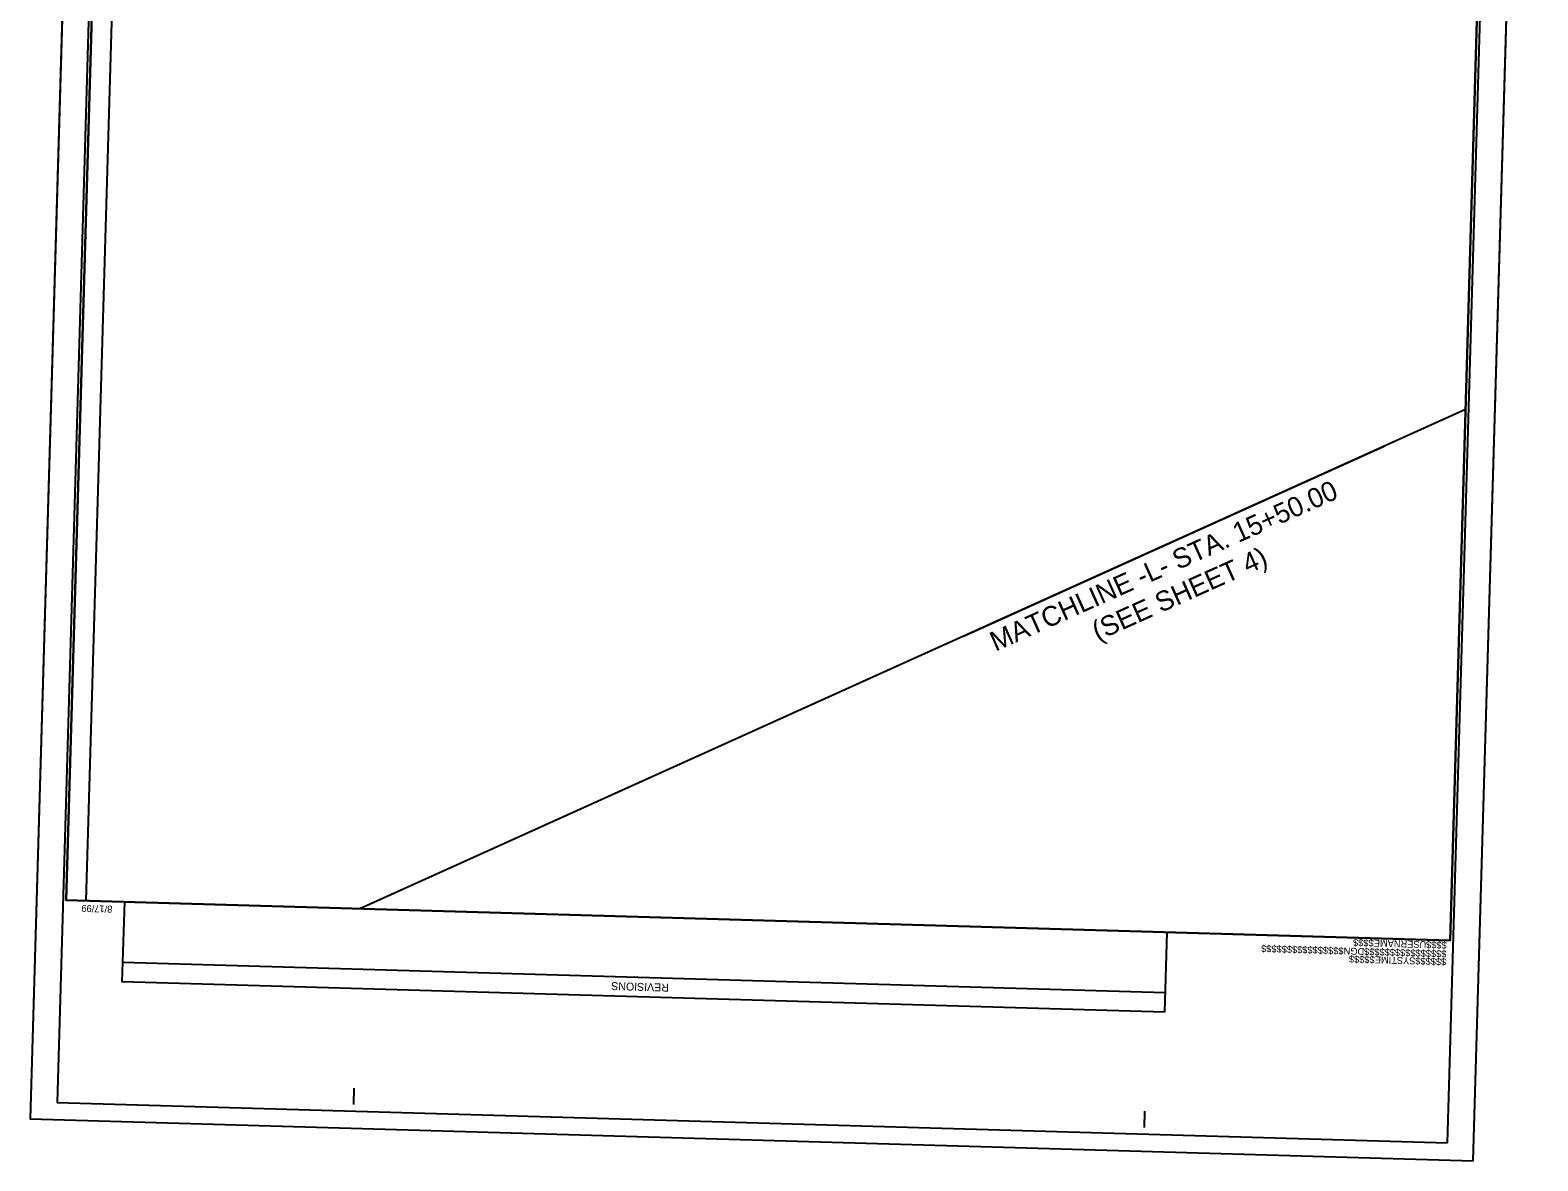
# Model space of a CAD drawing. Extents: x 2096987 to 2098130, y 681809 to 686842.
# Drawn here: x 2096987 to 2098130, y 685128 to 685985 of the extents above; entities that cross this region are included whole.
import ezdxf

# ---------------------------------------------------------------- set-up
doc = ezdxf.new("R2010")
doc.units = 0
for name, color, linetype in [('Matchline', 7, 'Continuous'), ('Matchline Text', 7, 'Continuous'), ('Scratch_Level_6', 7, 'Continuous'), ('Sheet Block Revision CELL', 7, 'Continuous'), ('Sheet Cutting Line CELL', 7, 'Continuous'), ('Sheet Plan CELL', 7, 'Continuous'), ('Sheet Plot Border Inside CELL', 7, 'Continuous'), ('Sheet Plot Border Outside CELL', 7, 'Continuous')]:
    doc.layers.add(name, color=color, linetype=linetype)

msp = doc.modelspace()

# ---------------------------------------------------------------- linework, layer by layer
at = {"layer": 'Matchline'}
msp.add_line((2097694.7, 685525.6), (2098013.7, 685669.6), dxfattribs=at)
at = {"layer": 'Scratch_Level_6'}
msp.add_lwpolyline([(2098075.4, 685697.4), (2097236.8, 685318.9), (2097029.4, 685324.9), (2097061.3, 686424.4), (2097087.6, 686423.7), (2097093.4, 686623.6), (2097228.1, 686619.7), (2097231.4, 686733), (2098104.7, 686707.6)], close=True, dxfattribs=at)
at = {"layer": 'Sheet Block Revision CELL'}
msp.add_line((2097847.4, 685255.2), (2097057.1, 685278.2), dxfattribs=at)
msp.add_lwpolyline([(2097847, 685240.6), (2097056.7, 685263.6), (2097058.5, 685324.1), (2097848.8, 685301.2)], close=True, dxfattribs=at)
at = {"layer": 'Sheet Cutting Line CELL'}
for p, q in [((2097035.7, 686842.4), (2096986.8, 685159.6)), ((2098081.3, 685127.8), (2098130.3, 686810.6)), ((2096986.8, 685159.6), (2098081.3, 685127.8))]:
    msp.add_line(p, q, dxfattribs=at)
at = {"layer": 'Sheet Plan CELL'}
for p, q in [((2097014.1, 685325.4), (2097014.1, 685325.4)), ((2098063.7, 685294.9), (2098063.7, 685294.9)), ((2097232.2, 685170.5), (2097232.6, 685183)), ((2097832, 685153.1), (2097832.3, 685165.6))]:
    msp.add_line(p, q, dxfattribs=at)
for points in [[(2097057.7, 686824.8), (2097014.1, 685325.4), (2098063.7, 685294.9), (2098107.3, 686794.3)], [(2098063.7, 685294.9), (2097014.1, 685325.4), (2097051.9, 686624.8), (2097201.9, 686620.5), (2097207.7, 686820.4), (2098107.3, 686794.3)]]:
    msp.add_lwpolyline(points, close=True, dxfattribs=at)
at = {"layer": 'Sheet Plot Border Inside CELL'}
msp.add_lwpolyline([(2098061.7, 685141.4), (2098110.1, 686806.7), (2097055.6, 686837.4), (2097007.2, 685172.1)], close=True, dxfattribs=at)
at = {"layer": 'Sheet Plot Border Outside CELL'}
msp.add_lwpolyline([(2098081.3, 685127.8), (2098130.3, 686810.6), (2097035.7, 686842.4), (2096986.8, 685159.6)], close=True, dxfattribs=at)

# ---------------------------------------------------------------- texts
at = {"layer": 'Matchline Text'}
for s, p in [('MATCHLINE -L- STA. 15+50.00', (2097719, 685513.8)), ('(SEE SHEET 4)', (2097796.4, 685521.8))]:
    msp.add_text(s, height=15, rotation=24.122, dxfattribs=at).set_placement(p)
at = {"layer": 'Sheet Block Revision CELL'}
msp.add_text('REVISIONS', height=6, rotation=178.3348, dxfattribs=at).set_placement((2097471.3, 685262.1))
at = {"layer": 'Sheet Plan CELL'}
for s, p in [('8/17/99', (2097049.2, 685321.2)), ('$$$$$$$$$$$$$$$$DGN$$$$$$$$$$$$$$$$', (2098061.1, 685287.3)), ('$$$$USERNAME$$$$', (2098061.3, 685293.9)), ('$$$$$$SYSTIME$$$$$', (2098060.9, 685281.3))]:
    msp.add_text(s, height=5.25, rotation=178.3348, dxfattribs=at).set_placement(p)

doc.saveas('drawing.dxf')
